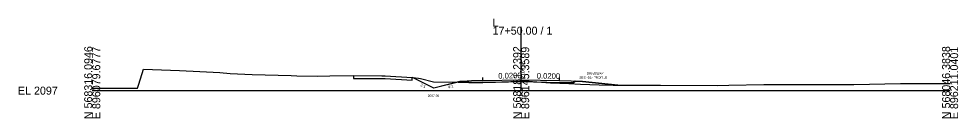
# Model space of a CAD drawing. Extents: x -26 to 1603, y -10 to 13527.
# Drawn here: x -25.7 to 302.8, y 4990.3 to 5025.2 of the extents above; entities that cross this region are included whole.
import ezdxf

# ---------------------------------------------------------------- set-up
doc = ezdxf.new("R2010")
doc.units = 0
for name, color, linetype in [('Default', 7, 'Continuous'), ('Exist XS Center Line Elevation Label', 7, 'Continuous'), ('Exist XS Ground Line', 7, 'Continuous'), ('Old_Level_61', 7, 'Continuous'), ('Old_Level_63', 7, 'Continuous'), ('Prop XS Ditch Slope Text', 7, 'Continuous'), ('Prop XS Ditch Standard Text', 7, 'Continuous'), ('Prop XS Earthwork Shape', 7, 'Continuous'), ('Prop XS EOT Tick Mark', 7, 'Continuous'), ('Prop XS Finish Grade', 7, 'Continuous'), ('Prop XS Finish Grade Earthwork', 7, 'Continuous'), ('Prop XS Finish Grade Paved Shoulder', 7, 'Continuous'), ('Prop XS Finish Grade Pavement', 7, 'Continuous'), ('Prop XS Side Slope Text', 7, 'Continuous'), ('Prop XS Subgrade Earthwork', 7, 'Continuous'), ('Prop XSC Text', 7, 'Continuous')]:
    doc.layers.add(name, color=color, linetype=linetype)

msp = doc.modelspace()

# ---------------------------------------------------------------- linework, layer by layer
at = {"layer": 'Exist XS Ground Line'}
for p, q in [((16.26, 5002.31), (17.9, 5007.48)), ((17.9, 5007.48), (30.49, 5007.1)), ((30.49, 5007.1), (32.84, 5007)), ((32.84, 5007), (35.27, 5006.86)), ((35.27, 5006.86), (44.6, 5006.34)), ((44.6, 5006.34), (48.24, 5006.01)), ((48.24, 5006.01), (55.88, 5005.7)), ((55.88, 5005.7), (65.02, 5005.41)), ((65.02, 5005.41), (69.57, 5005.3)), ((69.57, 5005.3), (71.56, 5005.22)), ((71.56, 5005.22), (78.68, 5005.13)), ((78.68, 5005.13), (83.13, 5005.22)), ((83.13, 5005.22), (91.36, 5005.29)), ((91.36, 5005.29), (101.26, 5005.25)), ((101.26, 5005.25), (101.8, 5005.24)), ((101.8, 5005.24), (102.4, 5005.21)), ((102.4, 5005.21), (111.85, 5004.67)), ((111.85, 5004.67), (112.72, 5004.49)), ((112.72, 5004.49), (113.08, 5004.45)), ((113.08, 5004.45), (114.09, 5004.34)), ((114.09, 5004.34), (114.84, 5004.27)), ((114.84, 5004.27), (119.31, 5003.11)), ((0, 5000.9), (15.84, 5000.89)), ((15.84, 5000.89), (16.26, 5002.31)), ((119.31, 5003.11), (134.11, 5002.95)), ((134.11, 5002.95), (143.28, 5003.13)), ((143.28, 5003.13), (149.5, 5003.3)), ((149.5, 5003.3), (150, 5003.31)), ((150, 5003.31), (151.4, 5003.36)), ((151.4, 5003.36), (153.94, 5003.21)), ((153.94, 5003.21), (160.2, 5002.77)), ((160.2, 5002.77), (166.67, 5002.51)), ((166.67, 5002.51), (170.71, 5002.28)), ((170.71, 5002.28), (177.31, 5002.09)), ((177.31, 5002.09), (182.19, 5001.95)), ((182.19, 5001.95), (195.96, 5001.91)), ((195.96, 5001.91), (197.12, 5001.9)), ((197.12, 5001.9), (198.74, 5001.9)), ((198.74, 5001.9), (218.7, 5001.8)), ((218.7, 5001.8), (222.61, 5001.91)), ((222.61, 5001.91), (234.89, 5002.11)), ((234.89, 5002.11), (245.17, 5002.21)), ((245.17, 5002.21), (251.95, 5002.21)), ((251.95, 5002.21), (264.41, 5002.13)), ((264.41, 5002.13), (265.11, 5002.17)), ((265.11, 5002.17), (266.29, 5002.18)), ((266.29, 5002.18), (282.61, 5002.46)), ((282.61, 5002.46), (283.62, 5002.46)), ((283.62, 5002.46), (284.8, 5002.49)), ((284.8, 5002.49), (298.59, 5002.49)), ((298.59, 5002.49), (300, 5002.48))]:
    msp.add_line(p, q, dxfattribs=at)
at = {"layer": 'Old_Level_61'}
for p, q in [((91.36, 5005.29), (91.36, 5004.29)), ((91.36, 5004.29), (92.36, 5004.29)), ((92.36, 5004.29), (101.26, 5004.25)), ((101.26, 5004.25), (101.8, 5004.24)), ((101.8, 5004.24), (102.4, 5004.21)), ((102.4, 5004.21), (111.85, 5003.67)), ((111.85, 5003.67), (111.85, 5004.67))]:
    msp.add_line(p, q, dxfattribs=at)
at = {"layer": 'Old_Level_63'}
for p, q in [((150, 5000), (150, 5022.44)), ((0, 5000), (150, 5000)), ((150, 5000), (300, 5000))]:
    msp.add_line(p, q, dxfattribs=at)
at = {"layer": 'Prop XS Earthwork Shape'}
for points in [[(113.08, 5004.45), (114.09, 5004.34), (114.84, 5004.27), (119.31, 5003.11), (127.92, 5003.02), (119.45, 5000.9), (111.94, 5004.65), (112.72, 5004.49)], [(131.48, 5002.98), (131.08, 5003.38), (128.57, 5003.18), (127.92, 5003.02)], [(153.94, 5003.21), (158.61, 5002.89), (150, 5003.06), (136.57, 5002.79), (131.76, 5002.69), (131.48, 5002.98), (134.11, 5002.95), (143.28, 5003.13), (149.5, 5003.3), (150, 5003.31), (151.4, 5003.36)], [(182.19, 5001.95), (183.81, 5001.94), (171.43, 5003.18), (168.93, 5003.38), (168.24, 5002.69), (163.43, 5002.79), (158.61, 5002.89), (160.2, 5002.77), (166.67, 5002.51), (170.71, 5002.28), (177.31, 5002.09)]]:
    msp.add_lwpolyline(points, close=True, dxfattribs=at)
at = {"layer": 'Prop XS EOT Tick Mark'}
for p, q in [((136.57, 5003.58), (136.57, 5004.58)), ((163.43, 5003.58), (163.43, 5004.58))]:
    msp.add_line(p, q, dxfattribs=at)
at = {"layer": 'Prop XS Finish Grade'}
for p, q in [((132.57, 5003.5), (131.08, 5003.38)), ((167.43, 5003.5), (168.93, 5003.38))]:
    msp.add_line(p, q, dxfattribs=at)
at = {"layer": 'Prop XS Finish Grade Earthwork'}
for p, q in [((119.45, 5000.9), (111.94, 5004.65)), ((128.57, 5003.18), (119.45, 5000.9)), ((131.08, 5003.38), (128.57, 5003.18)), ((168.93, 5003.38), (171.43, 5003.18)), ((171.43, 5003.18), (183.81, 5001.94))]:
    msp.add_line(p, q, dxfattribs=at)
at = {"layer": 'Prop XS Finish Grade Paved Shoulder'}
for p, q in [((136.57, 5003.58), (132.57, 5003.5)), ((163.43, 5003.58), (167.43, 5003.5))]:
    msp.add_line(p, q, dxfattribs=at)
at = {"layer": 'Prop XS Finish Grade Pavement'}
for p, q in [((136.57, 5003.58), (150, 5003.85)), ((150, 5003.85), (163.43, 5003.58))]:
    msp.add_line(p, q, dxfattribs=at)
at = {"layer": 'Prop XS Subgrade Earthwork'}
for p, q in [((131.76, 5002.69), (131.08, 5003.38)), ((136.57, 5002.79), (131.76, 5002.69)), ((150, 5003.06), (136.57, 5002.79)), ((163.43, 5002.79), (150, 5003.06)), ((163.43, 5002.79), (168.24, 5002.69)), ((168.24, 5002.69), (168.93, 5003.38))]:
    msp.add_line(p, q, dxfattribs=at)

# ---------------------------------------------------------------- texts
at = {"layer": 'Default'}
for rotation, p in [(1.1458, (142, 5004.19)), (358.8542, (155.43, 5004.24))]:
    msp.add_text('0.0200', height=2, rotation=rotation, dxfattribs=at).set_placement(p)
at = {"layer": 'Exist XS Center Line Elevation Label'}
msp.add_text('2100.31', height=1, rotation=90, dxfattribs=at).set_placement((150.5, 4996.03))
at = {"layer": 'Old_Level_63'}
for s, p in [('L', (140, 5022.44)), ('17+50.00 / 1', (140, 5019.64)), ('EL 2097', (-26, 4998.6))]:
    msp.add_text(s, height=2.8, dxfattribs=at).set_placement(p)
for s, p in [('N 568316.0946', (0, 4990)), ('E 896079.6777', (2.8, 4990)), ('N 568181.2392', (150, 4990)), ('E 896145.3589', (152.8, 4990)), ('N 568046.3838', (300, 4990)), ('E 896211.0401', (302.8, 4990))]:
    msp.add_text(s, height=2.8, rotation=90, dxfattribs=at).set_placement(p)
at = {"layer": 'Prop XS Ditch Slope Text'}
msp.add_text('4:1', height=1, rotation=14.0358, dxfattribs=at).set_placement((124.51, 5000.71))
at = {"layer": 'Prop XS Ditch Standard Text'}
msp.add_text('SEE -D1- PROFILE', height=0.8, rotation=360, dxfattribs=at).set_placement((170.36, 5004.2))
for s, p in [('DRIVEWAY', (172.97, 5005.64)), ('2097.90', (117.33, 4997.79))]:
    msp.add_text(s, height=0.8, dxfattribs=at).set_placement(p)
at = {"layer": 'Prop XS Side Slope Text'}
msp.add_text('2:1', height=1, rotation=333.4357, dxfattribs=at).set_placement((114.63, 5001.69))
at = {"layer": 'Prop XSC Text'}
msp.add_text(' 2100.85', height=1.2, rotation=90, dxfattribs=at).set_placement((151.2, 5003.85))

doc.saveas('drawing.dxf')
